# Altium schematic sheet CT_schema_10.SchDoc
size 146 x 119 mm
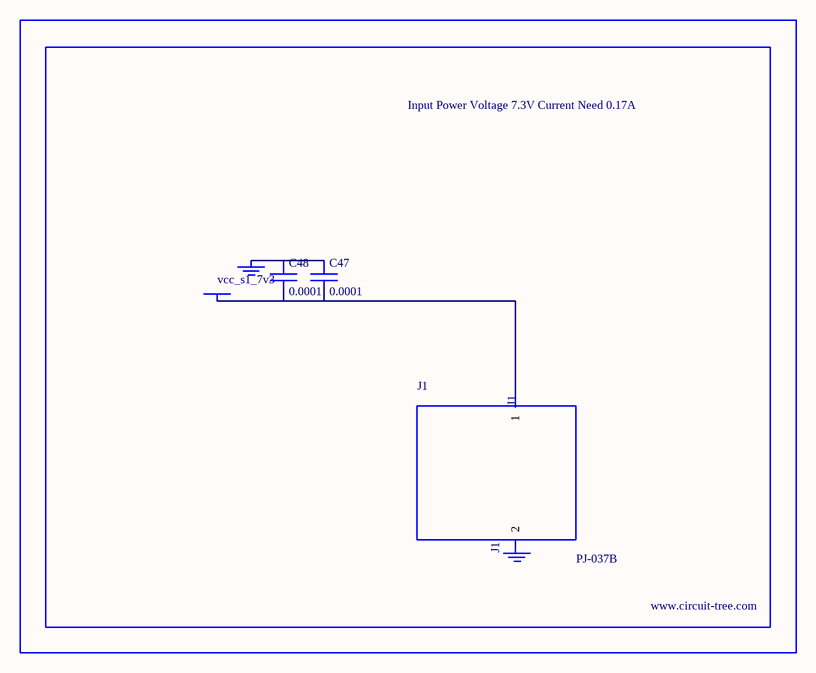
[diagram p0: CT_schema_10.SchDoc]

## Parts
BORDER9  (no value)
C47  0.0001  [EXV-9H]
C48  0.0001  [EXV-9H]
GND_INSTANCE_9_0  (no value)
GND_INSTANCE_9_1  (no value)
J1  PJ-037B  [PJ-037B_PACKAGE]
POWER_INSTANCE_9_0  vcc_s1_7v3

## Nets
NetC47_1: C47.1 C48.1 GND_INSTANCE_9_0.0(GND)
NetC47_2: C47.2 C48.2 J1.1 POWER_INSTANCE_9_0.0(PWR)

Not connected (* = marked no-connect by the designer): GND_INSTANCE_9_1 0(GND); J1 2

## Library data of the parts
BORDER9 = BORDER_PAGE9
C47 C48 = EDK107M035A9HAA
GND_INSTANCE_9_0 GND_INSTANCE_9_1 = GND
POWER_INSTANCE_9_0 = PWR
